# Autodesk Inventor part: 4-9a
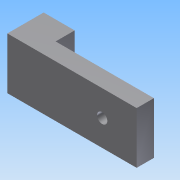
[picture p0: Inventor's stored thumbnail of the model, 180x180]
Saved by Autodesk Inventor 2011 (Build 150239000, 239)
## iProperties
Created: 2014-03
Part Number: 4-9a
Document SubType Name: Modeling
Designer: Administrator
Density: 1 g/cm^3
Author: Administrator
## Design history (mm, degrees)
sketch "草图1"
  geometry: L1 (0, 0)-(75, 0); L2 (75, 0)-(75, 10); L3 (75, 10)-(18, 10); L4 (18, 10)-(18, 21.05); L5 (18, 21.05)-(0, 21.05); L6 (0, 21.05)-(0, 0)
  constraints: 12 end point, 4 parallel, 1 horizontal, 1 perpendicular
  dimensions: "d0" = 75 distance of L1.start L1.end; "d1" = 10 distance of L1.end L2.end; "d2" = 18 distance of L4.end L5.end
extrude "拉伸1" new body sketch "草图1" distance "d3" = 30; taper "d4" = 0 deg
hole "Hole1" diameter "d7" = 6; stored, may be unused: countersink angle "d11" = 90 deg, drill point angle "d13" = 118 deg; dims "d5" = 20, "d6" = 15, "d8" = 6, "d9" = 4, "d10" = 2, "d12" = 8
node "实体1"
